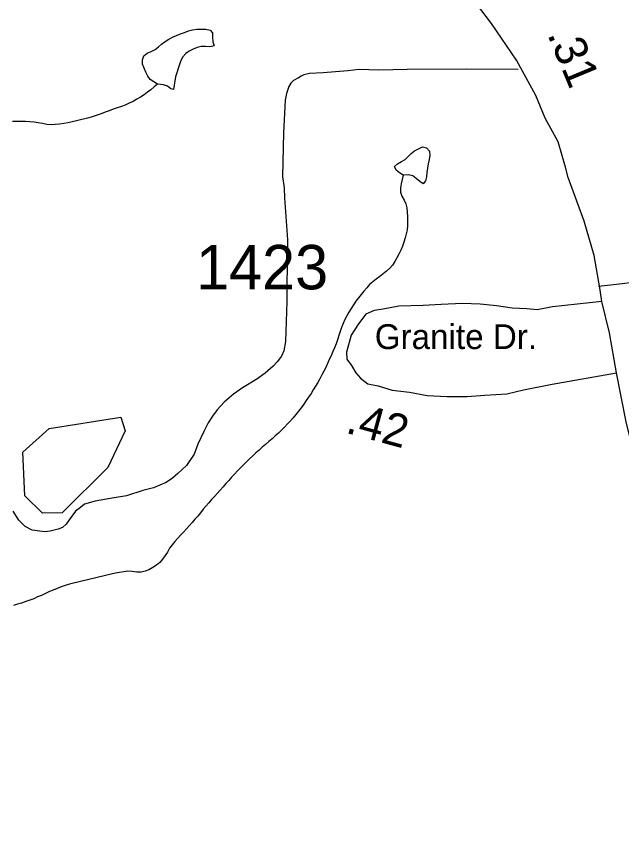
# Model space of a CAD drawing. Extents: x 1950930 to 2061844, y 904556 to 1017002.
# Drawn here: x 1983863 to 1986179, y 969967 to 973118 of the extents above; entities that cross this region are included whole.
import ezdxf

# ---------------------------------------------------------------- set-up
doc = ezdxf.new("R2010")
doc.units = 0
for name, color, linetype in [('Exist Hydrographic Misc Water Feature', 7, 'Continuous'), ('Exist Road Non-System Type 51', 7, 'Continuous'), ('Exist Road Primary NC Attributed', 7, 'Continuous'), ('Exist Road Primary NC Mileage Hundredths English Label', 7, 'Continuous'), ('Exist Road Primary US Structure Standard Bridge CELL', 7, 'Continuous'), ('Exist Road Secondary Type 51 Attributed', 7, 'Continuous'), ('Exist Road Secondary Type 51 Label', 7, 'Continuous'), ('Exist Road Secondary Type 51 Number Label', 7, 'Continuous')]:
    doc.layers.add(name, color=color, linetype=linetype)

msp = doc.modelspace()

# ---------------------------------------------------------------- linework, layer by layer
at = {"layer": 'Exist Hydrographic Misc Water Feature'}
for points in [[(1984402.6, 972858.7), (1984388.3, 972867.3), (1984374.9, 972876.5), (1984365.1, 972889.1), (1984358.3, 972904.8), (1984351.3, 972919.7), (1984345.4, 972935.4), (1984344.6, 972951), (1984350.7, 972967.3), (1984363, 972976.9), (1984378.8, 972983.1), (1984393.2, 972991), (1984406.1, 973001.5), (1984418.4, 973011.8), (1984431.7, 973022.2), (1984445.7, 973031), (1984460.4, 973038.1), (1984475.2, 973045.1), (1984490.6, 973051.4), (1984506, 973056.8), (1984521.3, 973062.3), (1984536.9, 973066.9), (1984553.5, 973068.9), (1984569.9, 973068.6), (1984587.2, 973068.3), (1984604.6, 973065.4), (1984613.2, 973055.4), (1984612.8, 973038.2), (1984614.2, 973020.9), (1984618.9, 973005.3), (1984603.2, 973001.5), (1984586.5, 973002.6), (1984570.3, 973003), (1984554.6, 972999.1), (1984539, 972992.9), (1984524.4, 972985.1), (1984511.1, 972975.4), (1984500, 972963.4), (1984492.2, 972949.6), (1984487.1, 972933.3), (1984482, 972917.8), (1984476.8, 972902.3), (1984472.1, 972886), (1984468.8, 972870.5), (1984467, 972854.1), (1984463.9, 972837.7), (1984453.5, 972840.5), (1984441, 972851.4), (1984425.4, 972855.9), (1984402.6, 972858.7)], [(1984402.6, 972858.7), (1984390.1, 972848.3), (1984377.6, 972837.1), (1984364.7, 972827.5), (1984351.3, 972817.9), (1984337.4, 972809.2), (1984323.3, 972800.4), (1984308.9, 972792.6), (1984294.3, 972785.5), (1984279.4, 972778.4), (1984264.2, 972773), (1984248.6, 972767.6), (1984232.8, 972762.2), (1984217.4, 972756.7), (1984202.1, 972751.3), (1984186.7, 972745), (1984171.1, 972739.6), (1984155.7, 972734.2), (1984139.9, 972729.7), (1984123.9, 972725.9), (1984108.2, 972722.1), (1984092, 972717.5), (1984076, 972713.7), (1984060, 972710.8), (1984043.6, 972707.8), (1984027.4, 972704.9), (1984011.4, 972703.6), (1983995.2, 972703.1), (1983979, 972704.2), (1983962.6, 972707.8), (1983946.2, 972710.6), (1983930, 972712.6), (1983913.8, 972713.8), (1983897.2, 972714.9), (1983880.8, 972715.3), (1983864.3, 972715.6), (1983847.9, 972715.1)], [(1985343.2, 972510.3), (1985328.8, 972518.8), (1985315.7, 972528.8), (1985309.3, 972543), (1985321.4, 972553.3), (1985336.4, 972562), (1985350.6, 972569.9), (1985362, 972582.1), (1985373.7, 972593.3), (1985386.7, 972603.7), (1985401.6, 972610.7), (1985417.2, 972618.6), (1985432.2, 972614.3), (1985443.9, 972601.7), (1985445.1, 972586.8), (1985442.4, 972569.7), (1985438.9, 972553.4), (1985436.7, 972537), (1985433.8, 972520.6), (1985431.8, 972504.3), (1985429.1, 972487.9), (1985419.7, 972477.4), (1985406.5, 972486), (1985392.8, 972496.9), (1985379.5, 972507), (1985364.1, 972511.5), (1985343.2, 972510.3)], [(1985343.2, 972510.3), (1985339.9, 972493.9), (1985335.8, 972477.5), (1985333.3, 972461.2), (1985333.5, 972445.7), (1985338.5, 972430), (1985346.5, 972415), (1985353.4, 972400), (1985356.5, 972384.5), (1985358.4, 972367.9), (1985359.8, 972351.5), (1985360.2, 972334.3), (1985359.6, 972317.9), (1985357.9, 972301.5), (1985355.1, 972285.2), (1985351, 972269.7), (1985346.1, 972254.1), (1985340.3, 972238.7), (1985334.2, 972223.3), (1985327, 972207.8), (1985319.2, 972193.2), (1985310.8, 972179.4), (1985301.8, 972165.7), (1985291.7, 972153.6), (1985279.8, 972142.3), (1985266.9, 972131.9), (1985253.4, 972122.4), (1985239.6, 972112), (1985226.5, 972102.4), (1985214.4, 972091.2), (1985203.5, 972079), (1985192.7, 972066.2), (1985182.4, 972053.3), (1985172.4, 972040.4), (1985162.3, 972027.5), (1985152.9, 972013.7), (1985144.1, 972000), (1985135.3, 971986.1), (1985127.1, 971972.4), (1985119.7, 971957.7), (1985113.3, 971942.3), (1985107.6, 971926.8), (1985102.5, 971911.4), (1985097.3, 971895.9), (1985092.2, 971880.3), (1985086.5, 971865), (1985080.1, 971849.5), (1985073.7, 971834.8), (1985067, 971819.3), (1985060.4, 971804.8), (1985053.4, 971789.3), (1985046.7, 971774.6), (1985039.3, 971760.1), (1985032.1, 971745.4), (1985024.3, 971730.9), (1985016.1, 971716.2), (1985007.7, 971702.5), (1984999.1, 971688.7), (1984990.3, 971675), (1984981.3, 971661.1), (1984972, 971647.4), (1984962.6, 971633.7), (1984952.8, 971619.8), (1984942.9, 971607), (1984932.7, 971594.1), (1984922.2, 971581.9), (1984911.3, 971569.9), (1984900.3, 971557.8), (1984888.8, 971545.7), (1984877.1, 971534.5), (1984865.2, 971523.2), (1984853.1, 971512), (1984841, 971500.8), (1984828.7, 971490.3), (1984816.2, 971479.2), (1984803.7, 971468.7), (1984791.6, 971457.5), (1984779.1, 971447.1), (1984767, 971435.9), (1984754.9, 971424.6), (1984743.2, 971413.3), (1984731.3, 971401.3), (1984720.2, 971390.1), (1984708.8, 971378), (1984697.5, 971366), (1984686.4, 971353.8), (1984675.3, 971341.8), (1984664.3, 971329.7), (1984653.4, 971317.6), (1984642.5, 971304.7), (1984631.9, 971292.6), (1984620.8, 971280.6), (1984609.9, 971268.5), (1984599, 971255.5), (1984588.2, 971243.4), (1984577.5, 971231.3), (1984567.1, 971218.4), (1984556.6, 971205.5), (1984545.9, 971193.5), (1984535.3, 971180.5)], [(1984212.3, 971391.3), (1984037.4, 971217.7), (1983962.4, 971216), (1983895.3, 971282.9), (1983887.3, 971450.4), (1983987.4, 971540.3), (1984262.4, 971583.8), (1984279.4, 971531), (1984212.3, 971391.3)], [(1984535.3, 971180.5), (1984524.4, 971168.5), (1984513.3, 971156.4), (1984502.1, 971144.3), (1984491, 971132.2), (1984480.1, 971120.2), (1984469.5, 971108), (1984458.8, 971095.2), (1984449, 971082.2), (1984440.3, 971067.6), (1984431.5, 971053.9), (1984422.3, 971040.1), (1984411.2, 971028), (1984398.7, 971017.7), (1984385, 971008.9), (1984369.8, 971000.1), (1984354.8, 970994.7), (1984339.5, 970990.9), (1984323, 970991.2), (1984306.2, 970993.3), (1984289.6, 970994.5), (1984273.4, 970992.4), (1984257.2, 970989.4), (1984241.2, 970986.4), (1984225, 970982.6), (1984209, 970979.7), (1984193, 970976), (1984177.1, 970971.3), (1984161.1, 970967.5), (1984145.1, 970963.8), (1984129.1, 970960.1), (1984113.3, 970956.3), (1984097.1, 970952.5), (1984081.3, 970948.7), (1984065.7, 970944.2), (1984049.7, 970939.6), (1984034.3, 970934.1), (1984018.5, 970928.7), (1984003.6, 970922.4), (1983988.8, 970916.2), (1983973.8, 970909.1), (1983958.9, 970902), (1983943.7, 970895.8), (1983928.7, 970888.7), (1983913.4, 970883.3), (1983898, 970877.8), (1983882.2, 970872.5), (1983866.6, 970867.8), (1983850.8, 970863.2)]]:
    msp.add_lwpolyline(points, dxfattribs=at)
at = {"layer": 'Exist Road Non-System Type 51'}
for points in [[(1985782.8, 972915), (1985587.2, 972915.5), (1985358.4, 972914.7), (1985248.2, 972912.2), (1985175, 972914.7), (1985131.2, 972909.6), (1985036.2, 972901.2), (1984984.1, 972899.6), (1984963, 972894.5), (1984953, 972889.4), (1984942, 972882.7), (1984923.5, 972872.6), (1984913.4, 972861.7), (1984905, 972849.1), (1984896.6, 972823), (1984890.8, 972797.8), (1984884.8, 972671.6), (1984881.4, 972505), (1984887.4, 972461.2), (1984889, 972423.4), (1984900, 972262.8), (1984898.2, 972081.9), (1984898.2, 972026.4), (1984892.4, 971873.2), (1984885.6, 971837.9), (1984877.2, 971817.8), (1984861.2, 971795.9), (1984845.2, 971779.1), (1984815, 971752.1), (1984783, 971729.4), (1984728.4, 971696.6), (1984693, 971672.2), (1984657.6, 971641.1), (1984630.8, 971612.5), (1984613.1, 971587.2), (1984596.2, 971562), (1984579.5, 971529.2), (1984557.6, 971481.2), (1984542.4, 971441.8), (1984513.9, 971398.8), (1984480.1, 971367.7), (1984460, 971350), (1984435.6, 971334.1), (1984386.8, 971313), (1984346.4, 971302.9), (1984283.4, 971282.8), (1984229.5, 971273.5), (1984163.9, 971262.6), (1984123.5, 971250.8), (1984108.4, 971238.1), (1984088.1, 971224.7), (1984063.8, 971191.1), (1984052.9, 971174.2), (1984039.4, 971161.6), (1984022.5, 971154.9), (1983992.2, 971148.1), (1983971.2, 971145.6), (1983923.2, 971151.5), (1983896.4, 971164.9), (1983871.1, 971189.4), (1983850.1, 971223.9)], [(1986090.6, 972084.8), (1986171.1, 972094.1), (1986230.8, 972101.8)]]:
    msp.add_lwpolyline(points, dxfattribs=at)
at = {"layer": 'Exist Road Primary NC Attributed'}
for points in [[(1986103.8, 972027.1), (1986096.5, 972078.4), (1986074.4, 972202.8), (1986035.8, 972334.1), (1985974.8, 972500.9), (1985964.8, 972540.3), (1985936.6, 972637.2), (1985886.4, 972728.5), (1985850.6, 972814.6), (1985777.1, 972950), (1985681.8, 973090.2), (1985583.4, 973220.3), (1985515.3, 973308), (1985462.5, 973380.2), (1985410.5, 973464.8)], [(1986159.8, 971754.1), (1986132.4, 971906.6), (1986103.8, 972027.1)], [(1987411.2, 968556), (1987273.8, 968780), (1987177.8, 968941), (1987017.7, 969210.9), (1986987.9, 969262.3), (1986837.9, 969505.9), (1986750.3, 969651.5), (1986668.1, 969797.8), (1986618, 969895.9), (1986579, 969982.8), (1986548.1, 970055.4), (1986531.5, 970102.1), (1986523, 970141.5), (1986509.2, 970198.7), (1986482.5, 970291.7), (1986449.4, 970452.4), (1986396.5, 970657.4), (1986364.5, 970820.7), (1986352.7, 970904.6), (1986302.7, 971139.3), (1986246.2, 971365.5), (1986197.2, 971566.7), (1986159.8, 971754.1)]]:
    msp.add_lwpolyline(points, dxfattribs=at)
at = {"layer": 'Exist Road Secondary Type 51 Attributed'}
for points in [[(1986103.8, 972027.1), (1985914.3, 972006.1), (1985856.2, 971994.3), (1985816.3, 971998.3), (1985760.3, 972000.5), (1985700.3, 972010.5), (1985638.2, 972016.6), (1985570.2, 972018.8), (1985488.3, 972014.9), (1985420.2, 972011.1), (1985326.2, 972009.3), (1985266.3, 971997.5), (1985232.2, 971991.6), (1985200.1, 971977.7), (1985172.1, 971941.6), (1985144, 971897.8), (1985125.9, 971833.2)], [(1985125.9, 971833.2), (1985127.7, 971805.7), (1985145.8, 971781.7), (1985161.6, 971753.8), (1985179.6, 971733.6), (1985207.6, 971711.6), (1985247.6, 971703.6), (1985301.5, 971687.4), (1985367.5, 971679.3), (1985435.5, 971667.1), (1985511.5, 971663.1), (1985587.5, 971662.9), (1985655.4, 971668.7), (1985739.5, 971672.6), (1985803.5, 971688.5), (1985913.6, 971710.2), (1986159.8, 971754.1)]]:
    msp.add_lwpolyline(points, dxfattribs=at)

# ---------------------------------------------------------------- texts
at = {"layer": 'Exist Road Primary NC Mileage Hundredths English Label'}
msp.add_text('.31', height=125, rotation=292.5776, dxfattribs=at).set_placement((1985893.8, 973049.6))
at = {"layer": 'Exist Road Primary US Structure Standard Bridge CELL'}
msp.add_text('.42', height=125, rotation=344.744, dxfattribs=at).set_placement((1985119, 971525.2))
at = {"layer": 'Exist Road Secondary Type 51 Label'}
msp.add_text('Granite Dr.', height=95, dxfattribs=at).set_placement((1985234.4, 971844.6))
at = {"layer": 'Exist Road Secondary Type 51 Number Label'}
msp.add_text('1423', height=170, dxfattribs=at).set_placement((1984550.2, 972073.1))

doc.saveas('drawing.dxf')
